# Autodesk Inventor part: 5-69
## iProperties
Company: HERDT-Verlag
Shininess: 64.0
Length Units: 11269
Angle Units: 11279
Time Units: 11290
Mass Units: 11283
Length Display Precision: 3
Angle Display Precision: 2
Compacted: True
Part Number: 5-69
Document SubType Name: Modeling
Created: 2006-01
Material: Standard
Designer: Eichenseer
Checked By: G. Lehmann
Engr Approved By: M. Grouls
Project: Inventor 11 - Grundkurs
Density: 0.0
Volumn: 0.0
Area: 0.0
PropertySet Name: Model Information
Control State: 0
Master: False
Checked Out: False
Author: P. Tropf
Subject: Inventor 10 - Grundkurs
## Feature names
1. Extrusion1
